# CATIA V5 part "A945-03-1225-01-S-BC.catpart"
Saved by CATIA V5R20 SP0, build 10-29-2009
Part number: A945-03-1225-01-S-BC
Source: Unknown
Property "ARTICLENO": "A945-03-1225-01-S-BC"
Property "B": "125.000"
Property "BOMINFO": "A945-03-1225-01-S-BC"
Property "CODE": "A945-03-1225-01-S-BC"
Property "D1": "26.000"
Property "D2": "17.500"
Property "D5": "20.000"
Property "D6": "16.000"
Property "H": "57.000"
Property "H1": "44.000"
Property "H2": "60.000"
Property "H3": "28.000"
Property "L1": "250.000"
Property "L2": "25.000"
Property "L3": "100.000"
Property "L4": "100.000"
Property "L5": "55.000"
Property "L6": "145.000"
Property "LINA": "A945-03-1225-01-S-BC"
Property "N": "7.000"
Property "NB": "A945-03-1225-01-S-BC"
Property "NBSYN": "$CODE."
Property "NN": "A945-03"
Property "NT": "v driver sets replaceable inserts pisitive return"
Property "SUPPLIER": "CF"
Property "Z": "85.000"
Bounding box of the stored display mesh (mm): x -669.473 to -511.473, y 748.188 to 833.188, z 0 to 250
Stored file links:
  C:\Users\Utente\Desktop\3D files A945-03\A945-03-1225-01-S-BC.catpart
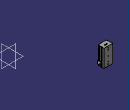
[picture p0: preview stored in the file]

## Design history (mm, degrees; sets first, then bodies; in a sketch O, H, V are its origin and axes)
Body1 "Geometry.1" (main body)
  Solid1 "A945-03-1225-01-S-BC.catpart": solid without history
